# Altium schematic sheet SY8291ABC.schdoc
size 127 x 101 mm
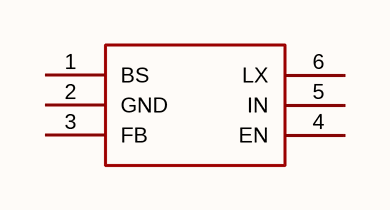
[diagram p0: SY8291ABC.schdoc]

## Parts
U?  sy8291abc  [SOT-23-6_L2.9-W1.6-P0.95-LS2.8-BR]  (value not drawn)

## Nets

Not connected (* = marked no-connect by the designer): U? 1(BS) 2(GND) 3(FB) 4(EN) 5(IN) 6(LX)

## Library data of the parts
U? = sy8291abc: 功能类型:降压型;工作电压:5V~40V;输出电压:-;输出电流:1.2A;输出类型:可调;; Manufacturer: Silergy(矽力杰); AddInBom: yes; ModelId: 18da8f6c14a34920b3e136b5c401a119; ModelName: SOT-23-6_L2.9-W1.6-H1.5-LS2.8-P0.95; ModelTransform: 110.73671,114.173,0,180,0,0,0.001,-0.003,0; Function: 降压型; Voltage - Supply: 5V~40V; Output Current: 1.2A; Frequency - Switching: 800kHz; Synchronous Rectifier: 否; Number of Outputs: 1; Topology: 降压式; Quiescent Current: 160uA; Switch tube (built-in/external): 内置; Output Type: 可调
